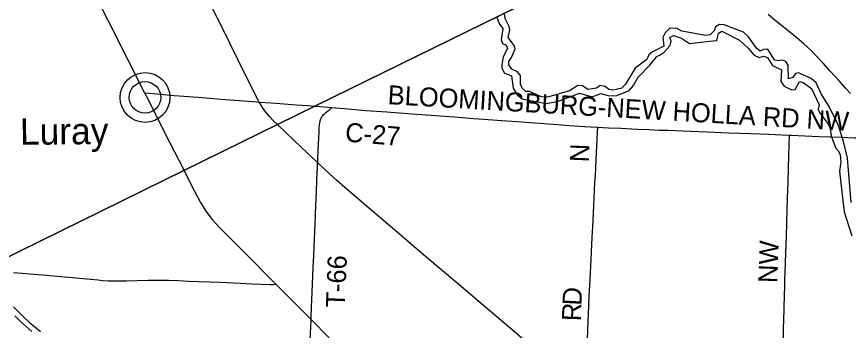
# Model space of a CAD drawing. Extents: x -51392 to 1635000, y 156707 to 696232.
# Drawn here: x 115578 to 128704, y 497882 to 502833 of the extents above; entities that cross this region are included whole.
import ezdxf

# ---------------------------------------------------------------- set-up
doc = ezdxf.new("R2010")
doc.units = 0
for name, color, linetype in [('GM_X_County_Road', 7, 'Continuous'), ('GM_X_County_Road_Text', 7, 'Continuous'), ('GM_X_Major_River', 7, 'Continuous'), ('GM_X_Rail_Line', 7, 'Continuous'), ('GM_X_State_Route', 7, 'Continuous'), ('GM_X_Township', 7, 'Continuous'), ('GM_X_Township_Road', 7, 'Continuous'), ('GM_X_Township_Road_Text', 7, 'Continuous'), ('GM_X_Unincorporated', 7, 'Continuous'), ('GM_X_Unincorporated_Text', 7, 'Continuous'), ('GM_X_US_Route', 7, 'Continuous')]:
    doc.layers.add(name, color=color, linetype=linetype)

msp = doc.modelspace()

# ---------------------------------------------------------------- linework, layer by layer
at = {"layer": 'GM_X_County_Road'}
for points in [[(116507, 503684), (116509, 503681), (116557, 503615), (116613, 503534), (116665, 503451), (116715, 503367), (116770, 503266), (116836, 503134), (116918, 502973), (117126, 502564), (117251, 502315), (117333, 502154), (117597, 501633)], [(117597, 501633), (117652, 501523), (117749, 501333), (117992, 500850), (118219, 500404)], [(117597, 501633), (117674, 501623), (118066, 501591), (118295, 501573), (118508, 501557), (118867, 501526), (119309, 501492), (119407, 501486), (119587, 501475), (119734, 501464), (119995, 501442), (120175, 501429), (120291, 501421)], [(120291, 501421), (120306, 501420), (120553, 501398)], [(120553, 501398), (120747, 501382), (121091, 501354), (121418, 501330), (121745, 501307), (122039, 501285), (122481, 501251), (122792, 501228), (123020, 501211), (123233, 501195), (123478, 501177), (123822, 501152), (123969, 501141), (124116, 501129), (124296, 501115), (124541, 501099), (124639, 501093), (124749, 501088)], [(124749, 501088), (124918, 501079), (125114, 501072), (125376, 501059), (125557, 501052), (125720, 501044), (125852, 501039), (126212, 501027), (126474, 501015), (126818, 501001), (127163, 500987), (127441, 500976), (127654, 500966), (127776, 500962)], [(127680, 497722), (127682, 497902), (127688, 498214), (127697, 498459), (127700, 498558), (127703, 498673), (127706, 498804), (127711, 498951), (127716, 499099), (127721, 499230), (127725, 499361), (127733, 499574), (127739, 499787), (127744, 499968), (127752, 500230), (127764, 500640), (127776, 500955), (127776, 500962)], [(127776, 500962), (127802, 500961), (128015, 500952), (128244, 500943), (128588, 500930), (128801, 500920), (128829, 500919)], [(118219, 500404), (118333, 500178), (118431, 499988), (118478, 499902), (118520, 499831), (118565, 499762), (118614, 499696), (118665, 499632), (118719, 499570), (118787, 499498), (119284, 498998), (119539, 498743), (119668, 498612)], [(115526, 498796), (115722, 498779), (116049, 498751), (116270, 498732), (116408, 498721), (116572, 498705), (116865, 498678), (116932, 498671), (117025, 498665), (117097, 498662), (117159, 498662), (117306, 498665), (117654, 498674), (117816, 498674), (117972, 498676), (118131, 498670), (118289, 498660), (118453, 498655), (118797, 498642), (119108, 498627), (119288, 498619), (119566, 498607), (119599, 498606), (119616, 498606), (119632, 498608), (119668, 498612)], [(119668, 498612), (119792, 498487), (120118, 498163), (120228, 498052)], [(120228, 498052), (120267, 498012), (120463, 497813), (120542, 497730), (120719, 497536), (120885, 497355), (121094, 497125), (121227, 496979), (121392, 496797), (121857, 496289), (122089, 496035), (122310, 495793), (122532, 495552), (122830, 495224), (123162, 494862), (123361, 494644), (123516, 494474), (123725, 494244), (123924, 494026), (124101, 493832), (124269, 493652), (124360, 493558), (124395, 493522)]]:
    msp.add_lwpolyline(points, dxfattribs=at)
at = {"layer": 'GM_X_Major_River'}
for points in [[(123915, 501562), (123861, 501566), (123674, 501653), (123614, 501651), (123556, 501702), (123528, 501768), (123527, 501904), (123481, 501960), (123391, 502003), (123343, 502073), (123343, 502125), (123388, 502191), (123446, 502323), (123428, 502377), (123333, 502506), (123359, 502622), (123353, 502678), (123290, 502806), (123278, 502873)], [(123150, 502837), (123198, 502713), (123251, 502644), (123225, 502468), (123244, 502410), (123304, 502382), (123322, 502331), (123254, 502197), (123235, 502075), (123235, 502023), (123273, 501947), (123390, 501898), (123414, 501704), (123481, 501592), (123555, 501537), (123929, 501460), (124111, 501493), (124460, 501623), (124662, 501568), (124796, 501620), (124854, 501607), (124930, 501581), (125052, 501587), (125242, 501666), (125313, 501746), (125387, 501880), (125572, 502070), (125679, 502206), (125733, 502232), (125795, 502274), (125892, 502379), (125906, 502444), (125886, 502504), (125942, 502534), (126070, 502491), (126194, 502411), (126512, 502446), (126630, 502455), (126653, 502573), (126709, 502605), (126988, 502460), (127124, 502338), (127218, 502227), (127298, 502191), (127364, 502209), (127428, 502188), (127509, 502062), (127647, 501993), (127640, 501809), (127688, 501737), (127808, 501678), (127866, 501686), (127934, 501812), (127992, 501792), (128122, 501699), (128245, 501442), (128229, 501370), (128249, 501320), (128388, 501131), (128416, 501071), (128433, 500951), (128459, 500879), (128505, 500758), (128548, 500708), (128572, 500650)], [(128749, 499900), (128692, 500599), (128619, 500884), (128544, 501125), (128399, 501414), (128276, 501617), (128198, 501791), (128119, 501858), (127917, 501948), (127867, 501936), (127829, 501874), (127758, 501851), (127753, 502065), (127718, 502125), (127666, 502144), (127601, 502134), (127544, 502146), (127500, 502212), (127434, 502321), (127366, 502313), (127310, 502287), (127256, 502335), (127127, 502516), (127047, 502588), (126745, 502705), (126671, 502708), (126609, 502674), (126585, 502610), (126521, 502548), (126454, 502536), (126073, 502605), (125989, 502650), (125883, 502648), (125810, 502578), (125778, 502502), (125789, 502368), (125613, 502280), (125555, 502230), (125525, 502158), (125338, 502021), (125189, 501767), (125127, 501705), (124992, 501671), (124924, 501685), (124863, 501732), (124787, 501744), (124728, 501702), (124590, 501686), (124508, 501741), (124432, 501745), (124302, 501661), (123977, 501568), (123915, 501562)], [(128572, 500650), (128584, 500544), (128563, 500393), (128615, 499932), (128637, 499752), (128759, 499373)]]:
    msp.add_lwpolyline(points, dxfattribs=at)
at = {"layer": 'GM_X_Rail_Line'}
msp.add_lwpolyline([(123772, 497570), (123469, 497830), (122561, 498600), (122001, 499076), (121622, 499400), (121156, 499796), (120756, 500138), (120626, 500251), (120516, 500351), (120067, 500772), (119704, 501118), (119630, 501190), (119566, 501259), (119511, 501324), (119458, 501399), (119399, 501492), (119191, 501912), (118950, 502403), (118418, 503485)], dxfattribs=at)
at = {"layer": 'GM_X_State_Route'}
msp.add_lwpolyline([(128738, 501619), (128661, 501705), (128562, 501814), (128419, 501972), (128309, 502094), (128187, 502227), (128118, 502297), (128058, 502354), (127997, 502408), (127832, 502544), (127753, 502609), (127650, 502694), (127551, 502772), (127438, 502865)], dxfattribs=at)
at = {"layer": 'GM_X_Township'}
for points in [[(125597, 504028), (120292, 501424), (118218, 500406), (115281, 498964)], [(115281, 498964), (118218, 500406), (120292, 501424), (125597, 504028)]]:
    msp.add_lwpolyline(points, dxfattribs=at)
at = {"layer": 'GM_X_Township_Road'}
for points in [[(120228, 498052), (120228, 498093), (120233, 498254), (120241, 498483), (120253, 498746), (120259, 498877), (120268, 499057), (120273, 499205), (120288, 499565), (120301, 499860), (120308, 500073), (120317, 500254), (120326, 500467), (120331, 500582), (120338, 500729), (120350, 501008), (120354, 501090), (120356, 501122), (120362, 501155), (120369, 501187), (120379, 501218), (120385, 501233), (120393, 501248), (120401, 501262), (120411, 501275), (120422, 501287), (120434, 501299), (120458, 501320), (120485, 501339), (120517, 501364), (120553, 501398)], [(124588, 497745), (124594, 497890), (124602, 498136), (124607, 498267), (124615, 498431), (124628, 498677), (124643, 499005), (124661, 499349), (124675, 499612), (124687, 499858), (124697, 500087), (124704, 500218), (124711, 500333), (124717, 500448), (124724, 500579), (124740, 500890), (124746, 501021), (124748, 501076), (124749, 501088)], [(120185, 497045), (120187, 497124), (120192, 497238), (120198, 497369), (120204, 497501), (120208, 497632), (120212, 497730), (120217, 497828), (120223, 497943), (120227, 498025), (120228, 498052)]]:
    msp.add_lwpolyline(points, dxfattribs=at)
at = {"layer": 'GM_X_Unincorporated'}
for radius in [393, 249]:
    msp.add_circle((117604, 501558), radius, dxfattribs=at)
at = {"layer": 'GM_X_US_Route'}
for points in [[(115529, 498255), (115609, 498172), (115691, 498091), (115776, 498014), (115863, 497938), (115952, 497865)], [(115550, 498109), (115633, 498029), (115729, 497941), (115816, 497866)]]:
    msp.add_lwpolyline(points, dxfattribs=at)

# ---------------------------------------------------------------- texts
at = {"layer": 'GM_X_County_Road_Text'}
for s, rotation, p in [('BLOOMINGBURG-NEW HOLLA RD NW', 356.6765, (121428, 501453)), ('C-27', 355.4098, (120754, 500863)), ('NW', 88.0659, (127582, 498626))]:
    msp.add_text(s, height=300, rotation=rotation, dxfattribs=at).set_placement(p)
at = {"layer": 'GM_X_Township_Road_Text'}
for s, rotation, p in [('N', 87.6778, (124608, 500531)), ('T-66', 87.712, (120757, 498238)), ('D', 86.8241, (124489, 498268)), ('R', 88.1258, (124482, 498024))]:
    msp.add_text(s, height=300, rotation=rotation, dxfattribs=at).set_placement(p)
at = {"layer": 'GM_X_Unincorporated_Text'}
msp.add_text('Luray', height=417, rotation=0.5386, dxfattribs=at).set_placement((115632, 500810))

doc.saveas('drawing.dxf')
